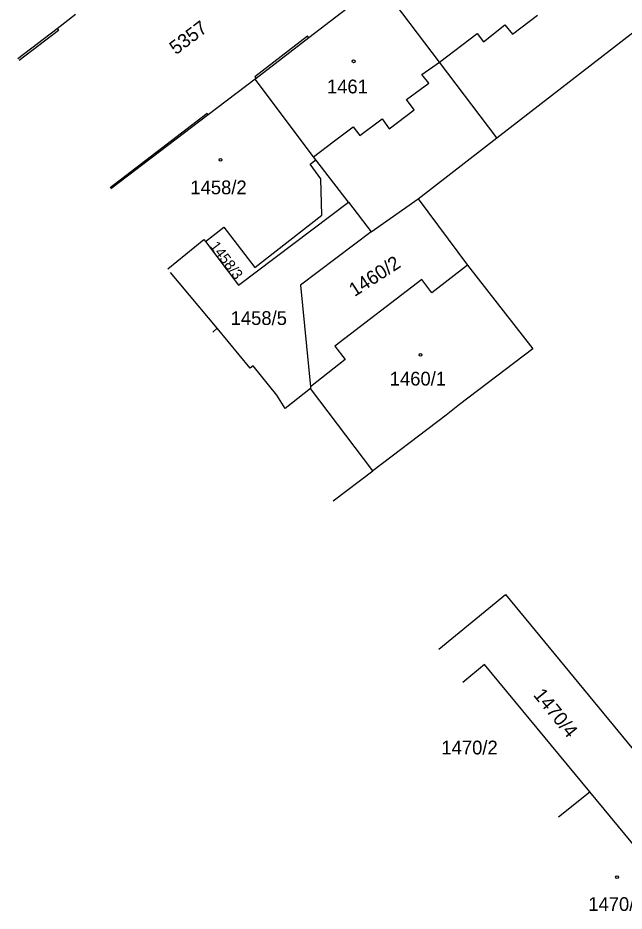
# Model space of a CAD drawing. Extents: x -821458 to -820266, y -1071458 to -1069826.
# Drawn here: x -821311.2 to -821236.4, y -1070661 to -1070550.7 of the extents above; entities that cross this region are included whole.
import ezdxf

# ---------------------------------------------------------------- set-up
doc = ezdxf.new("R2010")
doc.units = 0
for name, color, linetype in [('Vrstva 1', 7, 'Continuous'), ('Vrstva 2', 7, 'Continuous'), ('Vrstva 4', 7, 'Continuous'), ('Vrstva 5', 7, 'Continuous')]:
    doc.layers.add(name, color=color, linetype=linetype)

msp = doc.modelspace()

# ---------------------------------------------------------------- linework, layer by layer
at = {"layer": 'Vrstva 1'}
for p, q in [((-821252.09, -1070565.54), (-821233.85, -1070551.4)), ((-821261.77, -1070573.08), (-821252.09, -1070565.54)), ((-821270.4, -1070573.47), (-821274.43, -1070568.24)), ((-821270.4, -1070573.47), (-821267.59, -1070577.15)), ((-821267.59, -1070577.15), (-821261.77, -1070573.08)), ((-821261.77, -1070573.08), (-821255.69, -1070581.26)), ((-821286.58, -1070589.04), (-821292.37, -1070582.17)), ((-821287.14, -1070589.51), (-821286.58, -1070589.04)), ((-821275.08, -1070596.26), (-821275.06, -1070596.49)), ((-821267.38, -1070606.64), (-821275.06, -1070596.49)), ((-821244.47, -1070649.39), (-821240.59, -1070646.29))]:
    msp.add_line(p, q, dxfattribs=at)
for points in [[(-821266.51, -1070546.45), (-821275.28, -1070553.19), (-821281.79, -1070558.19), (-821281.93, -1070558.3)], [(-821252.09, -1070565.54), (-821259.16, -1070556.17), (-821266.51, -1070546.45)], [(-821311.2, -1070555.74), (-821306.37, -1070552.05), (-821304.07, -1070550.27)], [(-821281.93, -1070558.3), (-821287.7, -1070562.71), (-821299.73, -1070571.84)], [(-821274.43, -1070568.24), (-821274.72, -1070567.86), (-821281.93, -1070558.3)], [(-821288.04, -1070578.32), (-821285.79, -1070576.55), (-821281.97, -1070581.53), (-821273.7, -1070575.08), (-821273.82, -1070570.6), (-821275.13, -1070568.78), (-821274.43, -1070568.24)], [(-821288.04, -1070578.32), (-821283.95, -1070583.73), (-821270.4, -1070573.47)], [(-821267.59, -1070577.15), (-821276.3, -1070583.71), (-821275.08, -1070596.26)], [(-821292.69, -1070581.71), (-821288.23, -1070578.08), (-821288.04, -1070578.32)], [(-821255.69, -1070581.26), (-821260.08, -1070584.66), (-821261.35, -1070583.02), (-821272.07, -1070591.27), (-821270.79, -1070592.91), (-821275.08, -1070596.26)], [(-821255.69, -1070581.26), (-821247.62, -1070591.57), (-821256.68, -1070598.48), (-821258.35, -1070599.76), (-821267.38, -1070606.64)], [(-821275.06, -1070596.49), (-821278.2, -1070598.96), (-821279.24, -1070597.3), (-821282.17, -1070593.7), (-821282.52, -1070593.99), (-821286.58, -1070589.04)], [(-821272.27, -1070610.37), (-821267.38, -1070606.64)], [(-821259.22, -1070628.68), (-821251.01, -1070621.93), (-821233.48, -1070643.22)], [(-821240.59, -1070646.29), (-821253.58, -1070630.58), (-821256.29, -1070632.79)], [(-821230.52, -1070650.65), (-821234.51, -1070653.66), (-821240.59, -1070646.29)]]:
    msp.add_lwpolyline(points, dxfattribs=at)
at = {"layer": 'Vrstva 4'}
for p, q in [((-821250.13, -1070552.73), (-821247.05, -1070550.38)), ((-821253.71, -1070553.68), (-821251.07, -1070551.56)), ((-821251.07, -1070551.56), (-821250.13, -1070552.73)), ((-821306.19, -1070552.29), (-821311.03, -1070555.98)), ((-821306.37, -1070552.05), (-821306.19, -1070552.29)), ((-821259.16, -1070556.17), (-821254.51, -1070552.63)), ((-821254.51, -1070552.63), (-821253.71, -1070553.68)), ((-821275.44, -1070552.99), (-821281.95, -1070557.99)), ((-821275.28, -1070553.19), (-821275.44, -1070552.99)), ((-821261.33, -1070557.71), (-821259.16, -1070556.17)), ((-821281.95, -1070557.99), (-821281.79, -1070558.19)), ((-821260.47, -1070558.76), (-821261.33, -1070557.71)), ((-821263.23, -1070560.81), (-821260.47, -1070558.76)), ((-821262.3, -1070562.07), (-821263.23, -1070560.81)), ((-821287.84, -1070562.53), (-821299.83, -1070571.69)), ((-821287.7, -1070562.71), (-821287.84, -1070562.53)), ((-821265.35, -1070564.4), (-821262.3, -1070562.07)), ((-821269, -1070565.26), (-821266.25, -1070563.19)), ((-821266.25, -1070563.19), (-821265.35, -1070564.4)), ((-821272.3, -1070566.04), (-821269.82, -1070564.17)), ((-821269.82, -1070564.17), (-821269, -1070565.26)), ((-821274.72, -1070567.86), (-821272.3, -1070566.04))]:
    msp.add_line(p, q, dxfattribs=at)
at = {"layer": 'Vrstva 5'}
for centre in [(-821269.75, -1070556.08), (-821286.19, -1070568.24), (-821261.5, -1070592.32), (-821237.24, -1070656.83)]:
    msp.add_circle(centre, 0.175, dxfattribs=at)

# ---------------------------------------------------------------- texts
at = {"layer": 'Vrstva 2'}
for s, height, rotation, p in [('5357', 1.7, 37, (-821291.69, -1070555.34)), ('1458/3', 1.3, 307, (-821287.56, -1070578.91)), ('1460/2', 1.7, 33, (-821269.63, -1070585.2)), ('1470/4', 1.7, 309, (-821247.65, -1070634.36))]:
    msp.add_text(s, height=height, rotation=rotation, dxfattribs=at).set_placement(p)
for s, p in [('1461', (-821273.05, -1070560.04)), ('1458/2', (-821289.91, -1070572.5)), ('1458/5', (-821284.94, -1070588.64)), ('1460/1', (-821265.3, -1070596.12)), ('1470/2', (-821258.92, -1070641.67)), ('1470/3', (-821240.79, -1070661))]:
    msp.add_text(s, height=1.7, dxfattribs=at).set_placement(p)

doc.saveas('drawing.dxf')
